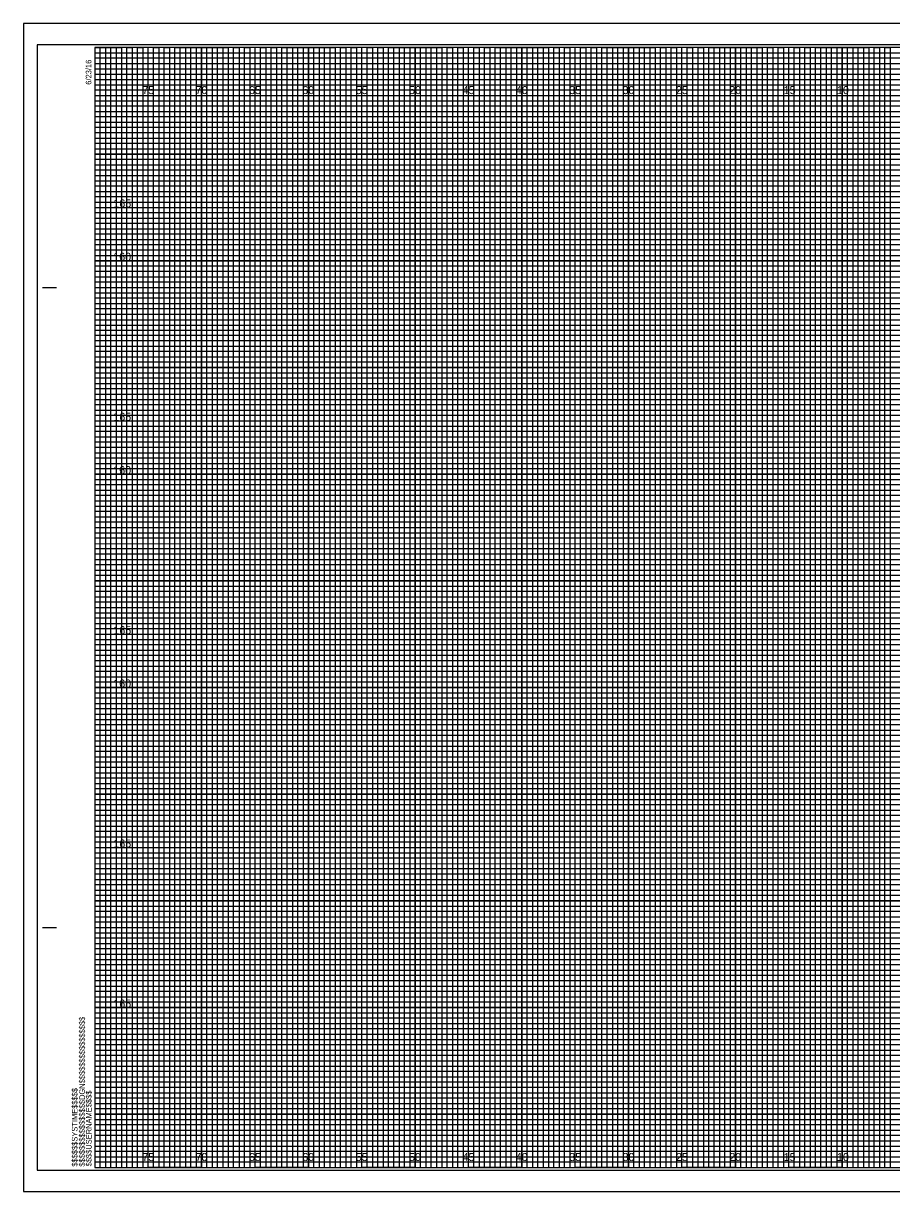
# Model space of a CAD drawing. Extents: x -7 to 162, y -2 to 107.
# Drawn here: x -6.7 to 74.6, y -2.3 to 107.3 of the extents above; entities that cross this region are included whole.
import ezdxf

# ---------------------------------------------------------------- set-up
doc = ezdxf.new("R2010")
doc.units = 0
for name, color, linetype in [('Prop CMT Slope Grass', 7, 'Continuous'), ('Prop XS Earthwork Shape', 7, 'Continuous'), ('Prop XS Elevation Labels', 7, 'Continuous'), ('Prop XS Hydro Elevations', 7, 'Continuous'), ('Prop XS SE Text', 7, 'Continuous'), ('Prop XS Side Slope Text', 7, 'Continuous'), ('Sheet Cross Section Grid Minor 2 CELL', 7, 'Continuous'), ('Sheet Cutting Line CELL', 7, 'Continuous'), ('Sheet DOT Grid CELL', 7, 'Continuous'), ('Sheet Plot Border Inside CELL', 7, 'Continuous'), ('Sheet Plot Border Outside CELL', 7, 'Continuous')]:
    doc.layers.add(name, color=color, linetype=linetype)

msp = doc.modelspace()

# ---------------------------------------------------------------- linework, layer by layer
at = {"layer": 'Prop XS Earthwork Shape'}
for p, q in [((-4.9, 82.5), (-3.65, 82.5)), ((-4.85, 82.5), (-3.6, 82.5)), ((-4.9, 22.5), (-3.65, 22.5)), ((-4.85, 22.5), (-3.6, 22.5)), ((0, 0), (0, 0)), ((0, 0), (0, 0)), ((0, 0), (0, 0)), ((0, 0), (0, 0)), ((0, 0), (0, 0)), ((0, 0), (0, 0)), ((0, 0), (0, 0))]:
    msp.add_line(p, q, dxfattribs=at)
msp.add_lwpolyline([(160, 105), (0, 105), (0, 0), (160, 0)], close=True, dxfattribs=at)
at = {"layer": 'Prop XS Hydro Elevations'}
for p, q in [((0, 104.5), (130, 104.5)), ((130, 103.99), (0, 103.99)), ((0, 103.99), (0, 103.5)), ((0, 103.5), (130, 103.5)), ((130, 102.95), (0, 102.95)), ((0, 102.95), (0, 102)), ((0, 102), (160, 102))]:
    msp.add_line(p, q, dxfattribs=at)
for points in [[(0, 101.5), (135, 101.5), (160, 101.5), (160, 101), (0, 101)], [(0, 100.5), (160, 100.5), (160, 99.5), (0, 99.5)], [(0, 99), (160, 99), (160, 98.5), (0, 98.49)], [(0, 98), (160, 98), (160, 97), (0, 97)], [(0, 96.5), (160, 96.5), (160, 96), (0, 96)], [(0, 95.5), (160, 95.5), (160, 94.5), (0, 94.5)], [(0, 94), (160, 94), (160, 93.5), (0, 93.5)], [(0, 93), (160, 93), (160, 92), (0, 92)], [(0, 91.5), (160, 91.5), (160, 91), (0, 91)], [(0, 90.5), (160, 90.5), (160, 89.5), (0, 89.5)], [(0, 89), (160, 89), (160, 88.5), (0, 88.5)], [(0, 88), (160, 88), (160, 86.98), (160, 86.5), (160, 86), (0, 86)], [(0, 87), (160, 87), (160, 86.5), (0, 86.5)], [(0, 85.5), (160, 85.5), (160, 84.5), (0, 84.52)], [(0, 84.52), (160, 84.5), (160, 84), (0, 84)], [(0, 83.5), (160, 83.5), (160, 83), (0, 83)], [(0, 82), (160, 82), (160, 81.5), (0, 81.5)], [(0, 81), (160, 81), (160, 80.5), (0, 80.5)], [(-0.04, 79.45), (160, 79.45), (160, 78.94), (-0.04, 78.94)], [(0, 78.5), (160, 78.5), (160, 78), (0, 78)], [(0, 77), (160, 77), (160, 76.5), (0, 76.5)], [(0, 76), (160, 76), (160, 75.5), (0, 75.5)], [(0, 74.5), (160, 74.5), (160, 74), (0, 74)], [(0, 73.5), (160, 73.5), (160, 73), (0, 73)], [(0, 72), (160, 72), (160, 71.5), (0, 71.5)], [(0, 71), (160, 71), (160, 70.5), (0, 70.5)], [(0, 69.5), (160, 69.5), (160, 68.99), (0, 69)], [(0, 68.5), (160, 68.5), (160, 68), (0, 68)], [(0, 67), (160, 67), (160, 66.5), (0, 66.5)], [(0, 66), (160, 66), (160, 65.5), (0, 65.5)], [(0, 64.5), (160, 64.5), (160, 64), (0, 64)], [(0, 63.5), (160, 63.5), (160, 63), (0, 63)], [(0, 62), (160, 62), (160, 61.5), (0, 61.5)], [(0, 61), (160, 61), (160, 60.5), (0, 60.5)], [(0, 59.5), (160, 59.5), (160, 59), (0, 59)], [(0, 58.5), (160.03, 58.45), (160, 58), (0, 58)], [(0, 57), (160, 57), (160, 56.5), (0, 56.5)], [(0, 56), (160, 56), (160, 55.5), (0, 55.5)], [(0, 54.5), (160, 54.5), (160, 54), (0, 54)], [(0, 53.5), (160, 53.5), (160, 53), (0, 53)], [(0, 52), (160, 52), (160, 51.5), (0, 51.5)], [(0, 51), (160, 51), (160, 50.5), (0, 50.5)], [(0, 49.5), (160, 49.5), (160, 49), (0, 49)], [(0, 48.5), (160, 48.5), (160, 48), (0, 48)], [(0, 47), (160, 47), (160, 46.5), (0, 46.5)], [(0, 46), (160, 46), (160, 45.5), (0, 45.5)], [(0, 44.5), (160, 44.5), (160, 44), (0, 44)], [(0, 43.5), (160, 43.5), (160, 43), (0, 43)], [(0, 42), (160, 42), (160, 41.5), (0, 41.5)], [(0, 41), (160, 41), (160, 40.5), (0, 40.5)], [(0, 39.5), (160, 39.5), (160, 38.99), (0, 39)], [(0, 38.5), (160, 38.5), (160, 38), (0, 38)], [(0, 37), (160, 37), (160, 36.5), (0, 36.5)], [(0, 36), (160, 36), (160, 35.5), (0, 35.5)], [(0, 34.5), (160, 34.5), (160, 34), (0, 34)], [(0, 33.5), (160, 33.5), (160, 33), (0, 33)], [(0, 32), (160, 32), (160, 31.5), (0, 31.5)], [(0, 31), (160, 31), (160, 30.5), (0, 30.5)], [(0, 29.5), (160, 29.5), (160, 29), (0, 29)], [(0, 28.5), (160.03, 28.46), (160, 28), (0, 28)], [(0, 27), (160, 27), (160, 26.5), (0, 26.5)], [(0, 26), (160, 26), (160, 25.5), (0, 25.5)], [(0, 24.5), (160, 24.5), (160, 24), (0, 24)], [(0, 23.5), (160, 23.5), (160, 23), (0, 23)], [(0, 22), (160, 22), (160, 21.5), (0, 21.5)], [(0, 21), (160, 21), (160, 20.5), (0, 20.5)], [(0, 19.5), (160, 19.5), (160, 19), (0, 19)], [(0, 18.5), (160, 18.5), (160, 18), (0, 18)], [(0, 17), (160, 17), (160, 16.5), (0, 16.5)], [(0, 16), (160, 16), (160, 15.5), (0, 15.5)], [(0, 14.5), (160, 14.5), (160, 14), (0, 14)], [(0, 13.5), (160, 13.5), (160, 13), (0, 13)], [(0, 12), (160, 12), (160, 11.5), (0, 11.5)], [(0, 11), (160, 11), (160, 10.5), (0, 10.5)], [(0, 9.5), (160, 9.5), (160, 9), (0, 9)], [(0, 8.5), (160, 8.5), (160, 8), (0, 8)], [(0, 7), (160, 7), (160, 6.5), (0, 6.5)], [(0, 6), (160, 6), (160, 5.5), (0, 5.5)], [(0, 4.5), (160, 4.5), (160, 4), (0, 4)], [(0, 3.5), (160, 3.5), (160, 3), (0, 3)], [(0, 2), (160, 2), (160, 1.5), (0, 1.5)], [(0, 1), (160, 1), (160, 0.5), (0, 0.5)]]:
    msp.add_lwpolyline(points, dxfattribs=at)
at = {"layer": 'Prop XS SE Text'}
for p, q in [((5, 105), (0, 105)), ((5, 0), (5, 105)), ((15, 105), (10, 105)), ((10, 105), (10, 0)), ((15, 0), (15, 105)), ((25, 105), (20, 105)), ((20, 105), (20, 0)), ((25, 0), (25, 105)), ((35, 105), (30, 105)), ((30, 105), (30, 0)), ((35, 0), (35, 105)), ((45, 105), (40, 105)), ((40, 105), (40, 0)), ((45, 0), (45, 105)), ((55, 105), (50, 105)), ((50, 105), (50, 0)), ((55, 0), (55, 105)), ((65, 105), (60, 105)), ((60, 105), (60, 0)), ((65, 0), (65, 105)), ((75, 105), (70, 105)), ((70, 105), (70, 0)), ((10, 0), (5, 0)), ((20, 0), (15, 0)), ((30, 0), (25, 0)), ((40, 0), (35, 0)), ((50, 0), (45, 0)), ((60, 0), (55, 0)), ((70, 0), (65, 0))]:
    msp.add_line(p, q, dxfattribs=at)
for points in [[(0, 100), (160, 100), (160, 95), (0, 95)], [(0, 90), (160, 90), (160, 85), (0, 85)], [(0, 80), (160, 80), (160, 75), (0, 75)], [(0, 70), (160, 70), (160, 65), (0, 65)], [(0, 60), (160, 60), (160, 55), (0, 55)], [(0, 50), (160, 50), (160, 45), (0, 45)], [(0, 40), (160, 40), (160, 35), (0, 35)], [(0, 30), (160, 30), (160, 25), (0, 25)], [(0, 20), (160, 20), (160, 15), (0, 15)], [(0, 10), (160, 10), (160, 5), (0, 5)]]:
    msp.add_lwpolyline(points, dxfattribs=at)
at = {"layer": 'Prop XS Side Slope Text'}
for points in [[(0, 105), (2.5, 105), (2.5, 0), (7.5, 0), (7.5, 105), (12.5, 105), (12.5, 0), (17.5, 0), (17.5, 105), (22.5, 105), (22.5, 0), (27.5, 0), (27.5, 105), (32.5, 105), (32.5, 0), (37.5, 0), (37.5, 105), (42.5, 105), (42.5, 0), (47.5, 0), (47.5, 105), (52.5, 105), (52.5, 0), (57.5, 0), (57.5, 105), (62.5, 105), (62.5, 0), (67.5, 0), (67.5, 105), (72.5, 105), (72.5, 0), (77.5, 0)], [(0, 102.5), (137.5, 102.5)], [(0, 92.5), (160, 92.5), (160, 97.5), (0, 97.5)], [(0, 82.5), (160, 82.5), (160, 87.5), (0, 87.5)], [(0, 72.5), (160, 72.5), (160, 77.5), (0, 77.5)], [(0, 62.5), (160, 62.5), (160, 67.5), (0, 67.5)], [(0, 52.5), (160, 52.5), (160, 57.5), (0, 57.5)], [(0, 42.5), (160, 42.5), (160, 47.5), (0, 47.5)], [(0, 32.5), (160, 32.5), (160, 37.5), (0, 37.5)], [(0, 22.5), (160, 22.5), (160, 27.5), (0, 27.5)], [(0, 12.5), (160, 12.5), (160, 17.5), (0, 17.5)], [(0, 2.5), (160, 2.5), (160, 7.5), (0, 7.5)]]:
    msp.add_lwpolyline(points, dxfattribs=at)
at = {"layer": 'Sheet Cross Section Grid Minor 2 CELL'}
for points in [[(0, 0), (0.5, 0), (0.5, 105), (1, 105), (1, 0)], [(1, 0), (1.5, 0), (1.5, 105), (2, 105), (2, 0)], [(2.5, 0), (3, 0), (3, 105), (3.5, 105), (3.5, 0)], [(3.5, 0), (4, 0), (4, 105), (4.5, 105), (4.5, 0)], [(5, 0), (5.5, 0), (5.5, 105), (6, 105), (6, 0)], [(6, 0), (6.5, 0), (6.5, 105), (7, 105), (7, 0)], [(7.5, 0), (8, 0), (8, 105), (8.5, 105), (8.5, 0)], [(8.5, 0), (9, 0), (9, 105), (9.5, 105), (9.5, 0)], [(10, 0), (10.5, 0), (10.5, 105), (11, 105), (11, 0)], [(11, 0), (11.5, 0), (11.5, 105), (12, 105), (12, 0)], [(12.5, 0), (13, 0), (13, 105), (13.5, 105), (13.5, 0)], [(13.5, 0), (14, 0), (14, 105), (14.5, 105), (14.5, 0)], [(15, 0), (15.5, 0), (15.5, 105), (16, 105), (16, 0)], [(16, 0), (16.5, 0), (16.5, 105), (17, 105), (17, 0)], [(17.5, 0), (18, 0), (18, 105), (18.5, 105), (18.5, 0)], [(18.5, 0), (19, 0), (19, 105), (19.5, 105), (19.5, 0)], [(20, 0), (20.5, 0), (20.5, 105), (21, 105), (21, 0)], [(21, 0), (21.5, 0), (21.5, 105), (22, 105), (22, 0)], [(22.5, 0), (23, 0), (23, 105), (23.5, 105), (23.5, 0)], [(23.5, 0), (24, 0), (24, 105), (24.5, 105), (24.5, 0)], [(25, 0), (25.5, 0), (25.5, 105), (26, 105), (26, 0)], [(26, 0), (26.5, 0), (26.5, 105), (27, 105), (27, 0)], [(27.5, 0), (28, 0), (28, 105), (28.5, 105), (28.5, 0)], [(28.5, 0), (29, 0), (29, 105), (29.5, 105), (29.5, 0)], [(30, 0), (30.5, 0), (30.5, 105), (31, 105), (31, 0)], [(31, 0), (31.5, 0), (31.5, 105), (32, 105), (32, 0)], [(32.5, 0), (33, 0), (33, 105), (33.5, 105), (33.5, 0)], [(33.5, 0), (34, 0), (34, 105), (34.5, 105), (34.5, 0)], [(35, 0), (35.5, 0), (35.5, 105), (36, 105), (36, 0)], [(36, 0), (36.5, 0), (36.5, 105), (37, 105), (37, 0)], [(37.5, 0), (38, 0), (38, 105), (38.5, 105), (38.5, 0)], [(38.5, 0), (39, 0), (39, 105), (39.5, 105), (39.5, 0)], [(40, 0), (40.5, 0), (40.5, 105), (41, 105), (41, 0)], [(41, 0), (41.5, 0), (41.5, 105), (42, 105), (42, 0)], [(42.5, 0), (43, 0), (43, 105), (43.5, 105), (43.5, 0)], [(43.5, 0), (44, 0), (44, 105), (44.5, 105), (44.5, 0)], [(45, 0), (45.5, 0), (45.5, 105), (46, 105), (46, 0)], [(46, 0), (46.5, 0), (46.5, 105), (47, 105), (47, 0)], [(47.5, 0), (48, 0), (48, 105), (48.5, 105), (48.5, 0)], [(48.5, 0), (49, 0), (49, 105), (49.5, 105), (49.5, 0)], [(50, 0), (50.5, 0), (50.5, 105), (51, 105), (51, 0)], [(51, 0), (51.5, 0), (51.5, 105), (52, 105), (52, 0)], [(52.5, 0), (53, 0), (53, 105), (53.5, 105), (53.5, 0)], [(53.5, 0), (54, 0), (54, 105), (54.5, 105), (54.5, 0)], [(55, 0), (55.5, 0), (55.5, 105), (56, 105), (56, 0)], [(56, 0), (56.5, 0), (56.5, 105), (57, 105), (57, 0)], [(57.5, 0), (58, 0), (58, 105), (58.5, 105), (58.5, 0)], [(58.5, 0), (59, 0), (59, 105), (59.5, 105), (59.5, 0)], [(60, 0), (60.5, 0), (60.5, 105), (61, 105), (61, 0)], [(61, 0), (61.5, 0), (61.5, 105), (62, 105), (62, 0)], [(62.5, 0), (63, 0), (63, 105), (63.5, 105), (63.5, 0)], [(63.5, 0), (64, 0), (64, 105), (64.5, 105), (64.5, 0)], [(65, 0), (65.5, 0), (65.5, 105), (66, 105), (66, 0)], [(66, 0), (66.5, 0), (66.5, 105), (67, 105), (67, 0)], [(67.5, 0), (68, 0), (68, 105), (68.5, 105), (68.5, 0)], [(68.5, 0), (69, 0), (69, 105), (69.5, 105), (69.5, 0)], [(70, 0), (70.5, 0), (70.5, 105), (71, 105), (71, 0)], [(71, 0), (71.5, 0), (71.5, 105), (72, 105), (72, 0)], [(72.5, 0), (73, 0), (73, 105), (73.5, 105), (73.5, 0)], [(73.5, 0), (74, 0), (74, 105), (74.5, 105), (74.5, 0)]]:
    msp.add_lwpolyline(points, dxfattribs=at)
at = {"layer": 'Sheet Cutting Line CELL'}
for p, q in [((161.65, 107.25), (-6.7, 107.25)), ((-6.7, 107.25), (-6.7, -2.25)), ((-6.7, -2.25), (161.65, -2.25))]:
    msp.add_line(p, q, dxfattribs=at)
at = {"layer": 'Sheet DOT Grid CELL'}
for p, q in [((5, 0), (5, 105)), ((10, 0), (10, 105)), ((15, 0), (15, 105)), ((20, 0), (20, 105)), ((25, 0), (25, 105)), ((30, 0), (30, 105)), ((35, 0), (35, 105)), ((40, 0), (40, 105)), ((45, 0), (45, 105)), ((50, 0), (50, 105)), ((55, 0), (55, 105)), ((60, 0), (60, 105)), ((65, 0), (65, 105)), ((70, 0), (70, 105)), ((0, 100), (160, 100)), ((0, 95), (160, 95)), ((0, 90), (160, 90)), ((0, 85), (160, 85)), ((0, 80), (160, 80)), ((0, 75), (160, 75)), ((0, 70), (160, 70)), ((0, 65), (160, 65)), ((0, 60), (160, 60)), ((0, 55), (160, 55)), ((0, 50), (160, 50)), ((0, 45), (160, 45)), ((0, 40), (160, 40)), ((0, 35), (160, 35)), ((0, 30), (160, 30)), ((0, 25), (160, 25)), ((0, 20), (160, 20)), ((0, 15), (160, 15)), ((0, 10), (160, 10)), ((0, 5), (160, 5))]:
    msp.add_line(p, q, dxfattribs=at)
at = {"layer": 'Sheet Plot Border Inside CELL'}
msp.add_lwpolyline([(-5.4, -0.25), (161.2, -0.25), (161.2, 105.25), (-5.4, 105.25)], close=True, dxfattribs=at)
at = {"layer": 'Sheet Plot Border Outside CELL'}
msp.add_lwpolyline([(-6.7, -2.25), (161.65, -2.25), (161.65, 107.25), (-6.7, 107.25)], close=True, dxfattribs=at)

# ---------------------------------------------------------------- texts
at = {"layer": 'Prop CMT Slope Grass'}
for s, p in [('75', (4.44, 100.62)), ('70', (9.43, 100.62)), ('65', (14.44, 100.62)), ('60', (19.43, 100.62)), ('55', (24.44, 100.62)), ('50', (29.43, 100.62)), ('45', (34.44, 100.62)), ('40', (39.43, 100.62)), ('35', (44.44, 100.62)), ('30', (49.43, 100.62)), ('25', (54.44, 100.62)), ('20', (59.43, 100.62)), ('15', (64.53, 100.62)), ('10', (69.52, 100.62)), ('75', (4.44, 0.62)), ('70', (9.43, 0.62)), ('65', (14.44, 0.62)), ('60', (19.43, 0.62)), ('55', (24.44, 0.62)), ('50', (29.43, 0.62)), ('45', (34.44, 0.62)), ('40', (39.43, 0.62)), ('35', (44.44, 0.62)), ('30', (49.43, 0.62)), ('25', (54.44, 0.62)), ('20', (59.43, 0.62)), ('15', (64.53, 0.62)), ('10', (69.52, 0.62))]:
    msp.add_text(s, height=0.75, dxfattribs=at).set_placement(p)
at = {"layer": 'Prop XS Earthwork Shape'}
for s, p in [('6/23/16', (-0.33, 101.5)), ('$$$$$$$$$$$$$$$$DGN$$$$$$$$$$$$$$$$', (-0.94, 0.09)), ('$$$$$$SYSTIME$$$$$', (-1.63, 0.09)), ('$$$$USERNAME$$$$', (-0.31, 0.12))]:
    msp.add_text(s, height=0.525, rotation=90, dxfattribs=at).set_placement(p)
at = {"layer": 'Prop XS Elevation Labels'}
for s, p in [('165', (1.73, 90)), ('160', (1.72, 85)), ('165', (1.73, 70)), ('160', (1.72, 65)), ('165', (1.73, 50)), ('160', (1.72, 45)), ('165', (1.73, 30)), ('165', (1.73, 15))]:
    msp.add_text(s, height=0.75, dxfattribs=at).set_placement(p)

doc.saveas('drawing.dxf')
